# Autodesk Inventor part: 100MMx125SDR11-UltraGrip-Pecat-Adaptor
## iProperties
Created: 2012-05
Part Number: 100MMx125SDR11-UltraGrip-Pecat-Adaptor
Document SubType Name: Modeling
Designer: D Cole
Density: 1 g/cm^3
Author: D Cole
